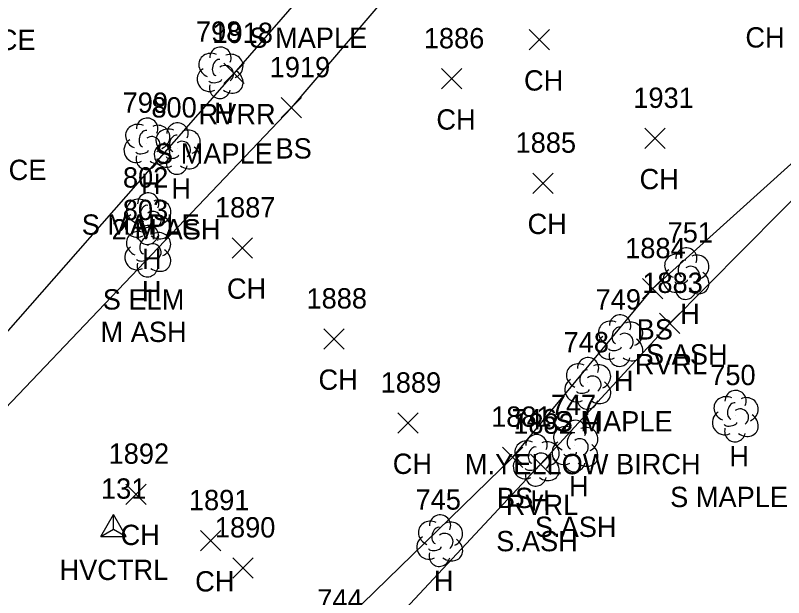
# Model space of a CAD drawing. Extents: x 1545627 to 1546562, y 571176 to 576667.
# Drawn here: x 1546211.1 to 1546286.7, y 572282.6 to 572339.9 of the extents above; entities that cross this region are included whole.
import ezdxf

# ---------------------------------------------------------------- set-up
doc = ezdxf.new("R2010")
doc.units = 0
for name, color, linetype in [('C_A', 7, 'Continuous'), ('C_I', 7, 'Continuous'), ('CPSM', 7, 'Continuous'), ('L_A', 7, 'Continuous'), ('L_C', 7, 'Continuous'), ('L_I', 7, 'Continuous'), ('L_TIC', 7, 'Continuous'), ('LAWE', 7, 'Continuous'), ('LELB', 7, 'Continuous'), ('LTD', 7, 'Continuous')]:
    doc.layers.add(name, color=color, linetype=linetype)

msp = doc.modelspace()

# ---------------------------------------------------------------- linework, layer by layer
at = {"layer": 'CPSM'}
for p, q in [((1546219.538, 572288.586), (1546220.788, 572290.751)), ((1546222.038, 572288.586), (1546220.788, 572290.751)), ((1546220.788, 572289.308), (1546220.788, 572290.751)), ((1546219.538, 572288.586), (1546220.788, 572289.308)), ((1546220.788, 572289.308), (1546220.788, 572289.308)), ((1546220.788, 572289.308), (1546222.038, 572288.586)), ((1546219.538, 572288.586), (1546222.038, 572288.586))]:
    msp.add_line(p, q, dxfattribs=at)
at = {"layer": 'L_TIC'}
for points in [[(1546261.669, 572336.472), (1546263.669, 572338.472)], [(1546263.669, 572336.472), (1546261.669, 572338.472)], [(1546231.645, 572333.154), (1546233.645, 572335.154)], [(1546233.645, 572333.154), (1546231.645, 572335.154)], [(1546253.053, 572332.629), (1546255.053, 572334.629)], [(1546255.053, 572332.629), (1546253.053, 572334.629)], [(1546237.283, 572329.782), (1546239.283, 572331.782)], [(1546239.283, 572329.782), (1546237.283, 572331.782)], [(1546273.034, 572326.766), (1546275.034, 572328.766)], [(1546275.034, 572326.766), (1546273.034, 572328.766)], [(1546262.021, 572322.353), (1546264.021, 572324.353)], [(1546264.021, 572322.353), (1546262.021, 572324.353)], [(1546232.459, 572315.983), (1546234.459, 572317.983)], [(1546234.459, 572315.983), (1546232.459, 572317.983)], [(1546272.8, 572311.974), (1546274.8, 572313.974)], [(1546274.8, 572311.974), (1546272.8, 572313.974)], [(1546274.487, 572308.557), (1546276.487, 572310.557)], [(1546276.487, 572308.557), (1546274.487, 572310.557)], [(1546241.463, 572307.026), (1546243.463, 572309.026)], [(1546243.463, 572307.026), (1546241.463, 572309.026)], [(1546248.764, 572298.747), (1546250.764, 572300.747)], [(1546250.764, 572298.747), (1546248.764, 572300.747)], [(1546259.052, 572295.387), (1546261.052, 572297.387)], [(1546261.052, 572295.387), (1546259.052, 572297.387)], [(1546261.797, 572294.702), (1546263.797, 572296.702)], [(1546263.797, 572294.702), (1546261.797, 572296.702)], [(1546222.003, 572291.749), (1546224.003, 572293.749)], [(1546224.003, 572291.749), (1546222.003, 572293.749)], [(1546229.333, 572287.179), (1546231.333, 572289.179)], [(1546231.333, 572287.179), (1546229.333, 572289.179)], [(1546232.54, 572284.495), (1546234.54, 572286.495)], [(1546234.54, 572284.495), (1546232.54, 572286.495)]]:
    msp.add_lwpolyline(points, dxfattribs=at)
at = {"layer": 'LAWE'}
for points in [[(1546079.438, 571966.947), (1546077.788, 571985.488), (1546075.176, 572034.738), (1546072.514, 572073.367), (1546072.957, 572091.545), (1546079.326, 572109.636), (1546089.965, 572133.875), (1546098.205, 572146.168), (1546103.269, 572146.803), (1546106.386, 572149.622), (1546130.143, 572181.263), (1546136.759, 572192.153), (1546140.729, 572200.768), (1546161.621, 572243.317), (1546187.565, 572282.786), (1546232.645, 572334.154), (1546255.297, 572360.235), (1546268.959, 572391.116)], [(1546121.265, 571957.172), (1546118.803, 571996.677), (1546114.937, 572038.101), (1546108, 572065.636), (1546104.767, 572084.584), (1546111.687, 572095.842), (1546118.703, 572113.935), (1546133.848, 572134.836), (1546145.167, 572135.646), (1546153.927, 572139.019), (1546169.651, 572160.036), (1546189.008, 572163.697), (1546206.714, 572193.958), (1546205.832, 572212.69), (1546216.066, 572227.226), (1546228.024, 572235.176), (1546234.868, 572265.766), (1546262.797, 572295.702), (1546275.487, 572309.557), (1546290.065, 572324.25)]]:
    msp.add_lwpolyline(points, dxfattribs=at)
at = {"layer": 'LELB'}
for points in [[(1546140.457, 572188.687), (1546144.086, 572197.302), (1546164.869, 572240.482), (1546191.763, 572281.913), (1546238.283, 572330.782), (1546258.38, 572354.309), (1546270.264, 572391.299)], [(1546138.465, 572142.662), (1546151.843, 572140.861), (1546169.324, 572161.725), (1546185.772, 572170.699), (1546202.895, 572194.936), (1546204.894, 572212.997), (1546215.164, 572227.989), (1546230.472, 572267.575), (1546260.052, 572296.387), (1546273.8, 572312.974), (1546290.068, 572327.618), (1546314.576, 572291.02)]]:
    msp.add_lwpolyline(points, dxfattribs=at)
at = {"layer": 'LTD'}
for p, q in [((1546231.264, 572334.275), (1546231.264, 572334.275)), ((1546231.264, 572334.275), (1546231.264, 572334.275)), ((1546224.06, 572327.284), (1546224.06, 572327.284)), ((1546224.06, 572327.284), (1546224.06, 572327.284)), ((1546227.042, 572326.82), (1546227.042, 572326.82)), ((1546227.042, 572326.82), (1546227.042, 572326.82)), ((1546224.16, 572319.923), (1546224.16, 572319.923)), ((1546224.16, 572319.923), (1546224.16, 572319.923)), ((1546224.144, 572316.727), (1546224.144, 572316.727)), ((1546224.144, 572316.727), (1546224.144, 572316.727)), ((1546277.075, 572314.514), (1546277.075, 572314.514)), ((1546277.075, 572314.514), (1546277.075, 572314.514)), ((1546270.568, 572307.924), (1546270.568, 572307.924)), ((1546270.568, 572307.924), (1546270.568, 572307.924)), ((1546267.41, 572303.717), (1546267.41, 572303.717)), ((1546267.41, 572303.717), (1546267.41, 572303.717)), ((1546281.922, 572300.485), (1546281.922, 572300.485)), ((1546281.922, 572300.485), (1546281.922, 572300.485)), ((1546266.154, 572297.545), (1546266.154, 572297.545)), ((1546266.154, 572297.545), (1546266.154, 572297.545)), ((1546262.344, 572296.138), (1546262.344, 572296.138)), ((1546262.344, 572296.138), (1546262.344, 572296.138)), ((1546252.855, 572288.233), (1546252.855, 572288.233)), ((1546252.855, 572288.233), (1546252.855, 572288.233))]:
    msp.add_line(p, q, dxfattribs=at)
for centre in [(1546231.31, 572335.709), (1546224.107, 572328.718), (1546227.089, 572328.254), (1546224.207, 572321.357), (1546224.191, 572318.161), (1546277.122, 572315.948), (1546270.614, 572309.358), (1546267.457, 572305.151), (1546281.968, 572301.919), (1546266.201, 572298.979), (1546262.391, 572297.572), (1546252.902, 572289.667)]:
    msp.add_arc(centre, 1.047, 335.52715, 180.95627, dxfattribs=at)
for centre, major_axis, ratio, start_param, end_param in [((1546230.472, 572334.941), (1.21, -0.512), 0.895232, 1.570796, 4.712389), ((1546232.305, 572334.858), (-1.141, -0.483), 0.949671, 1.570796, 4.712389), ((1546231.055, 572334.733), (-0.208, -0.792), 0.645439, 3.141593, 6.283185), ((1546230.18, 572333.566), (0.584, -1.042), 0.959034, 3.141593, 6.283185), ((1546231.764, 572334.108), (-0.5, 0.667), 0.989748, 3.141593, 6.283185), ((1546232.264, 572333.442), (-1.09, 0.792), 0.841452, 1.570796, 4.712389), ((1546230.805, 572333.525), (-0.625, -0.083), 0.423636, 0, 3.141593), ((1546231.264, 572332.775), (0.265, 1.061), 0.942809, 1.570796, 4.712389), ((1546223.268, 572327.95), (1.21, -0.512), 0.895232, 1.570796, 4.712389), ((1546225.102, 572327.867), (-1.141, -0.483), 0.949671, 1.570796, 4.712389), ((1546223.852, 572327.742), (-0.208, -0.792), 0.645439, 3.141593, 6.283185), ((1546226.251, 572327.486), (1.21, -0.512), 0.895232, 1.570796, 4.712389), ((1546228.084, 572327.403), (-1.141, -0.483), 0.949671, 1.570796, 4.712389), ((1546222.977, 572326.575), (0.584, -1.042), 0.959034, 3.141593, 6.283185), ((1546224.56, 572327.117), (-0.5, 0.667), 0.989748, 3.141593, 6.283185), ((1546226.834, 572327.278), (-0.208, -0.792), 0.645439, 3.141593, 6.283185), ((1546227.543, 572326.653), (-0.5, 0.667), 0.989748, 3.141593, 6.283185), ((1546225.06, 572326.451), (-1.09, 0.792), 0.841452, 1.570796, 4.712389), ((1546225.959, 572326.111), (0.584, -1.042), 0.959034, 3.141593, 6.283185), ((1546228.043, 572325.987), (-1.09, 0.792), 0.841452, 1.570796, 4.712389), ((1546224.06, 572325.784), (0.265, 1.061), 0.942809, 1.570796, 4.712389), ((1546223.602, 572326.534), (-0.625, -0.083), 0.423636, 0, 3.141593), ((1546226.584, 572326.07), (-0.625, -0.083), 0.423636, 0, 3.141593), ((1546227.043, 572325.32), (0.265, 1.061), 0.942809, 1.570796, 4.712389), ((1546223.369, 572320.589), (1.21, -0.512), 0.895232, 1.570796, 4.712389), ((1546225.202, 572320.506), (-1.141, -0.483), 0.949671, 1.570796, 4.712389), ((1546223.952, 572320.381), (-0.208, -0.792), 0.645439, 3.141593, 6.283185), ((1546223.077, 572319.214), (0.584, -1.042), 0.959034, 3.141593, 6.283185), ((1546224.661, 572319.756), (-0.5, 0.667), 0.989748, 3.141593, 6.283185), ((1546225.161, 572319.09), (-1.09, 0.792), 0.841452, 1.570796, 4.712389), ((1546223.702, 572319.173), (-0.625, -0.083), 0.423636, 0, 3.141593), ((1546223.352, 572317.394), (1.21, -0.512), 0.895232, 1.570796, 4.712389), ((1546224.161, 572318.423), (0.265, 1.061), 0.942809, 1.570796, 4.712389), ((1546225.185, 572317.311), (-1.141, -0.483), 0.949671, 1.570796, 4.712389), ((1546223.935, 572317.186), (-0.208, -0.792), 0.645439, 3.141593, 6.283185), ((1546223.061, 572316.019), (0.584, -1.042), 0.959034, 3.141593, 6.283185), ((1546224.644, 572316.561), (-0.5, 0.667), 0.989748, 3.141593, 6.283185), ((1546225.144, 572315.894), (-1.09, 0.792), 0.841452, 1.570796, 4.712389), ((1546276.283, 572315.18), (1.21, -0.512), 0.895232, 1.570796, 4.712389), ((1546278.117, 572315.097), (-1.141, -0.483), 0.949671, 1.570796, 4.712389), ((1546224.144, 572315.227), (0.265, 1.061), 0.942809, 1.570796, 4.712389), ((1546223.686, 572315.977), (-0.625, -0.083), 0.423636, 0, 3.141593), ((1546276.867, 572314.972), (-0.208, -0.792), 0.645439, 3.141593, 6.283185), ((1546275.992, 572313.805), (0.584, -1.042), 0.959034, 3.141593, 6.283185), ((1546277.575, 572314.347), (-0.5, 0.667), 0.989748, 3.141593, 6.283185), ((1546278.075, 572313.681), (-1.09, 0.792), 0.841452, 1.570796, 4.712389), ((1546277.076, 572313.014), (0.265, 1.061), 0.942809, 1.570796, 4.712389), ((1546276.617, 572313.764), (-0.625, -0.083), 0.423636, 0, 3.141593), ((1546269.776, 572308.59), (1.21, -0.512), 0.895232, 1.570796, 4.712389), ((1546271.609, 572308.507), (-1.141, -0.483), 0.949671, 1.570796, 4.712389), ((1546270.359, 572308.382), (-0.208, -0.792), 0.645439, 3.141593, 6.283185), ((1546271.068, 572307.757), (-0.5, 0.667), 0.989748, 3.141593, 6.283185), ((1546269.484, 572307.215), (0.584, -1.042), 0.959034, 3.141593, 6.283185), ((1546271.568, 572307.091), (-1.09, 0.792), 0.841452, 1.570796, 4.712389), ((1546270.109, 572307.174), (-0.625, -0.083), 0.423636, 0, 3.141593), ((1546270.568, 572306.424), (0.265, 1.061), 0.942809, 1.570796, 4.712389), ((1546266.619, 572304.383), (1.21, -0.512), 0.895232, 1.570796, 4.712389), ((1546268.452, 572304.3), (-1.141, -0.483), 0.949671, 1.570796, 4.712389), ((1546267.202, 572304.175), (-0.208, -0.792), 0.645439, 3.141593, 6.283185), ((1546267.911, 572303.55), (-0.5, 0.667), 0.989748, 3.141593, 6.283185), ((1546266.327, 572303.008), (0.584, -1.042), 0.959034, 3.141593, 6.283185), ((1546268.411, 572302.884), (-1.09, 0.792), 0.841452, 1.570796, 4.712389), ((1546266.952, 572302.967), (-0.625, -0.083), 0.423636, 0, 3.141593), ((1546267.411, 572302.217), (0.265, 1.061), 0.942809, 1.570796, 4.712389), ((1546281.13, 572301.152), (1.21, -0.512), 0.895232, 1.570796, 4.712389), ((1546282.963, 572301.069), (-1.141, -0.483), 0.949671, 1.570796, 4.712389), ((1546281.713, 572300.943), (-0.208, -0.792), 0.645439, 3.141593, 6.283185), ((1546282.422, 572300.318), (-0.5, 0.667), 0.989748, 3.141593, 6.283185), ((1546280.838, 572299.777), (0.584, -1.042), 0.959034, 3.141593, 6.283185), ((1546282.922, 572299.652), (-1.09, 0.792), 0.841452, 1.570796, 4.712389), ((1546281.463, 572299.735), (-0.625, -0.083), 0.423636, 0, 3.141593), ((1546265.363, 572298.212), (1.21, -0.512), 0.895232, 1.570796, 4.712389), ((1546265.946, 572298.003), (-0.208, -0.792), 0.645439, 3.141593, 6.283185), ((1546267.196, 572298.129), (-1.141, -0.483), 0.949671, 1.570796, 4.712389), ((1546281.922, 572298.985), (0.265, 1.061), 0.942809, 1.570796, 4.712389), ((1546261.552, 572296.805), (1.21, -0.512), 0.895232, 1.570796, 4.712389), ((1546263.386, 572296.722), (-1.141, -0.483), 0.949671, 1.570796, 4.712389), ((1546266.655, 572297.378), (-0.5, 0.667), 0.989748, 3.141593, 6.283185), ((1546262.136, 572296.597), (-0.208, -0.792), 0.645439, 3.141593, 6.283185), ((1546265.071, 572296.837), (0.584, -1.042), 0.959034, 3.141593, 6.283185), ((1546267.155, 572296.712), (-1.09, 0.792), 0.841452, 1.570796, 4.712389), ((1546262.844, 572295.972), (-0.5, 0.667), 0.989748, 3.141593, 6.283185), ((1546265.696, 572296.795), (-0.625, -0.083), 0.423636, 0, 3.141593), ((1546261.261, 572295.43), (0.584, -1.042), 0.959034, 3.141593, 6.283185), ((1546263.344, 572295.305), (-1.09, 0.792), 0.841452, 1.570796, 4.712389), ((1546266.155, 572296.045), (0.265, 1.061), 0.942809, 1.570796, 4.712389), ((1546261.886, 572295.388), (-0.625, -0.083), 0.423636, 0, 3.141593), ((1546262.344, 572294.638), (0.265, 1.061), 0.942809, 1.570796, 4.712389), ((1546252.064, 572288.9), (1.21, -0.512), 0.895232, 1.570796, 4.712389), ((1546253.897, 572288.817), (-1.141, -0.483), 0.949671, 1.570796, 4.712389), ((1546252.647, 572288.691), (-0.208, -0.792), 0.645439, 3.141593, 6.283185), ((1546253.355, 572288.066), (-0.5, 0.667), 0.989748, 3.141593, 6.283185), ((1546251.772, 572287.524), (0.584, -1.042), 0.959034, 3.141593, 6.283185), ((1546253.856, 572287.4), (-1.09, 0.792), 0.841452, 1.570796, 4.712389), ((1546252.397, 572287.483), (-0.625, -0.083), 0.423636, 0, 3.141593), ((1546252.856, 572286.733), (0.265, 1.061), 0.942809, 1.570796, 4.712389)]:
    msp.add_ellipse(centre, major_axis=major_axis, ratio=ratio, start_param=start_param, end_param=end_param, dxfattribs=at)

# ---------------------------------------------------------------- texts
at = {"layer": 'C_A'}
msp.add_text('HVCTRL', height=2, dxfattribs=at).set_placement((1546215.481, 572284.308))
at = {"layer": 'C_I'}
msp.add_text('131', height=2, dxfattribs=at).set_placement((1546219.56, 572292.308))
at = {"layer": 'L_A'}
for s, p in [('CH', (1546282.931, 572336.705)), ('CH', (1546261.158, 572332.472)), ('RVRR', (1546229.156, 572329.154)), ('H', (1546230.697, 572329.275)), ('CH', (1546252.542, 572328.629)), ('BS', (1546236.724, 572325.782)), ('CH', (1546272.523, 572322.766)), ('H', (1546223.493, 572322.284)), ('H', (1546226.476, 572321.82)), ('CH', (1546261.509, 572318.353)), ('H', (1546223.594, 572314.923)), ('CH', (1546231.947, 572311.983)), ('H', (1546223.577, 572311.727)), ('H', (1546276.508, 572309.514)), ('BS', (1546272.241, 572307.974)), ('RVRL', (1546272.053, 572304.557)), ('CH', (1546240.951, 572303.026)), ('H', (1546270.001, 572302.924)), ('H', (1546266.844, 572298.717)), ('H', (1546281.355, 572295.485)), ('CH', (1546248.253, 572294.747)), ('H', (1546265.588, 572292.545)), ('BS', (1546258.493, 572291.387)), ('H', (1546261.777, 572291.138)), ('RVRL', (1546259.364, 572290.702)), ('CH', (1546221.491, 572287.749)), ('H', (1546252.288, 572283.233)), ('CH', (1546228.821, 572283.179))]:
    msp.add_text(s, height=2, dxfattribs=at).set_placement(p)
at = {"layer": 'L_C'}
for s, p in [('S SPRUCE', (1546199.457, 572336.468)), ('S MAPLE', (1546234.148, 572336.675)), ('S MAPLE', (1546224.87, 572325.275)), ('S SPRUCE', (1546200.523, 572323.668)), ('S MAPLE', (1546217.666, 572318.284)), ('2 M ASH', (1546220.617, 572317.82)), ('S ELM', (1546219.735, 572310.923)), ('M ASH', (1546219.514, 572307.727)), ('S.ASH', (1546273.154, 572305.514)), ('S MAPLE', (1546264.174, 572298.924)), ('M.YELLOW BIRCH', (1546255.347, 572294.717)), ('S MAPLE', (1546275.528, 572291.485)), ('S.ASH', (1546262.233, 572288.545)), ('S.ASH', (1546258.423, 572287.138))]:
    msp.add_text(s, height=2, dxfattribs=at).set_placement(p)
at = {"layer": 'L_I'}
for s, p in [('798', (1546228.901, 572337.275)), ('1918', (1546230.519, 572337.154)), ('1886', (1546251.305, 572336.629)), ('1919', (1546236.149, 572333.782)), ('799', (1546221.69, 572330.284)), ('1931', (1546271.909, 572330.766)), ('800', (1546224.515, 572329.82)), ('1885', (1546260.328, 572326.353)), ('802', (1546221.72, 572322.923)), ('803', (1546221.703, 572319.727)), ('1887', (1546230.766, 572319.983)), ('751', (1546275.28, 572317.514)), ('1884', (1546271.107, 572315.974)), ('1883', (1546272.794, 572312.557)), ('1888', (1546239.77, 572311.026)), ('749', (1546268.197, 572310.924)), ('748', (1546265.048, 572306.717)), ('750', (1546279.473, 572303.485)), ('1889', (1546247.064, 572302.747)), ('747', (1546263.792, 572300.545)), ('1881', (1546257.926, 572299.387)), ('746', (1546259.927, 572299.138)), ('1882', (1546260.104, 572298.702)), ('1892', (1546220.31, 572295.749)), ('1891', (1546228.207, 572291.179)), ('745', (1546250.493, 572291.233)), ('1890', (1546230.76, 572288.495)), ('744', (1546240.834, 572281.406))]:
    msp.add_text(s, height=2, dxfattribs=at).set_placement(p)

doc.saveas('drawing.dxf')
